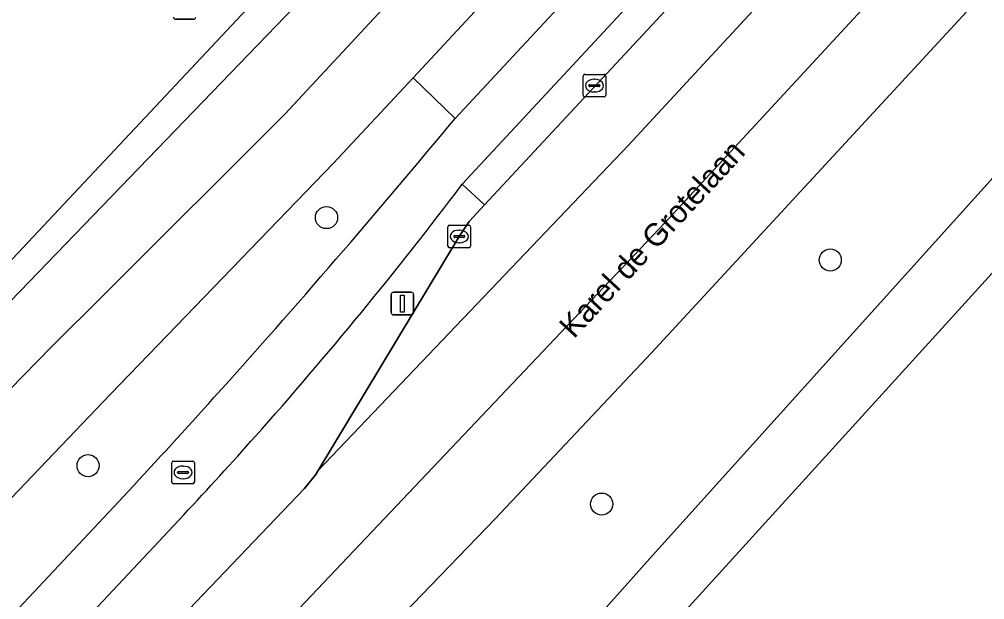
# Model space of a CAD drawing. Extents: x 159039 to 160102, y 381214 to 382524.
# Drawn here: x 159571.62 to 159614.28, y 381621.64 to 381647.3 of the extents above; entities that cross this region are included whole.
import ezdxf

# ---------------------------------------------------------------- set-up
doc = ezdxf.new("R2010")
doc.units = 0
for name, color, linetype in [('IMGEO_Afvalbak', 7, 'Continuous'), ('IMGEO_Berm_groen', 7, 'Continuous'), ('IMGEO_Boom', 7, 'Continuous'), ('IMGEO_Fietspad_gesloten', 7, 'Continuous'), ('IMGEO_Groenvoorziening', 7, 'Continuous'), ('IMGEO_Haag', 7, 'Continuous'), ('IMGEO_Kolk', 7, 'Continuous'), ('IMGEO_Lichtmast', 7, 'Continuous'), ('IMGEO_Openbare_ruimte_label', 7, 'Continuous'), ('IMGEO_OVBaan_gesloten', 7, 'Continuous'), ('IMGEO_Rijbaan_regionaal_gesloten', 7, 'Continuous'), ('IMGEO_Rioolput', 7, 'Continuous'), ('IMGEO_Voetpad_open', 7, 'Continuous')]:
    doc.layers.add(name, color=color, linetype=linetype)

msp = doc.modelspace()

# ---------------------------------------------------------------- linework, layer by layer
at = {"layer": 'IMGEO_Afvalbak'}
for p, q in [((159579.317, 381647.303), (159578.527, 381647.303)), ((159578.527, 381647.303), (159579.317, 381647.303))]:
    msp.add_line(p, q, dxfattribs=at)
for centre, start, end in [((159578.527, 381647.403), 180, 270), ((159578.527, 381647.403), 180, 270), ((159579.317, 381647.403), 270, 0), ((159579.317, 381647.403), 270, 0)]:
    msp.add_arc(centre, 0.1, start, end, dxfattribs=at)
at = {"layer": 'IMGEO_Berm_groen'}
for points in [[(159841.852, 381897.063), (159823.914, 381875.971), (159819.971, 381871.423), (159815.888, 381866.888), (159752.856, 381798.613), (159599.558, 381632.564), (159592.645, 381625.218), (159589.007, 381621.449), (159578.07, 381610.115), (159553.466, 381585.359)], [(159559.945, 381579.013), (159560.056, 381579.137), (159585.926, 381608.237), (159593.339, 381616.569), (159599.599, 381623.605), (159617.338, 381643.288), (159670.38, 381700.568), (159757.203, 381794.546)], [(159590.872, 381642.92), (159589.015, 381644.721), (159585.499, 381640.939), (159577.744, 381632.901), (159575.665, 381630.746), (159569.368, 381624.177), (159558.565, 381613.085), (159548.645, 381602.999), (159545.161, 381599.355), (159543.018, 381597.584), (159541.982, 381596.459), (159544.509, 381594.138), (159551.154, 381600.241), (159553.852, 381602.863), (159558.941, 381607.909), (159565.184, 381614.452), (159576.437, 381626.443)], [(159584.212, 381626.557), (159584.336, 381626.71), (159584.722, 381627.184), (159584.829, 381627.362), (159591.059, 381637.702), (159591.49, 381638.357), (159592.174, 381639.105), (159591.191, 381640.013)], [(159546.168, 381591.611), (159547.849, 381590.074), (159548.557, 381590.096), (159577.828, 381619.868), (159584.212, 381626.557)], [(159578.883, 381625.401), (159561.917, 381607.313)]]:
    msp.add_lwpolyline(points, dxfattribs=at)
for centre, radius, start, end in [((159286.321, 381895.111), 395.413, 318.01061, 320.37276), ((159447.443, 381748.616), 180.162, 318.3428, 322.92849), ((159274.657, 381905.991), 411.362, 317.19012, 317.97104), ((159449.828, 381746.393), 176.902, 316.84702, 318.36751)]:
    msp.add_arc(centre, radius, start, end, dxfattribs=at)
at = {"layer": 'IMGEO_Boom'}
for centre in [(159585.191, 381638.54), (159607.452, 381636.662), (159574.656, 381627.57), (159597.353, 381625.871)]:
    msp.add_circle(centre, 0.489, dxfattribs=at)
at = {"layer": 'IMGEO_Fietspad_gesloten'}
for points in [[(159835.156, 381908.672), (159832.541, 381905.347), (159832.075, 381904.754), (159821.782, 381892.503), (159813.565, 381883.06), (159802.783, 381871.052), (159791.475, 381858.62), (159743.819, 381807.067), (159624.348, 381677.828), (159617.523, 381670.775), (159605.021, 381658.14), (159590.872, 381642.92)], [(159591.191, 381640.013), (159607.377, 381657.444), (159619.167, 381669.166), (159626.019, 381676.247), (159694.686, 381750), (159745.746, 381805.265), (159767.026, 381828.298), (159776.532, 381838.557), (159790.971, 381854.296), (159805.539, 381870.374), (159816.536, 381882.828), (159825.133, 381893.111), (159830.877, 381899.559), (159834.614, 381904.005), (159837.348, 381907.14)], [(159576.437, 381626.443), (159565.184, 381614.452), (159558.941, 381607.909), (159553.852, 381602.863), (159551.154, 381600.241), (159544.509, 381594.138), (159544.059, 381593.709)], [(159561.917, 381607.313), (159578.883, 381625.401)]]:
    msp.add_lwpolyline(points, dxfattribs=at)
for centre, radius, start, end in [((159286.321, 381895.111), 395.413, 318.01061, 320.37276), ((159447.443, 381748.616), 180.162, 318.3428, 322.92849), ((159274.657, 381905.991), 411.362, 317.19012, 317.97104), ((159449.828, 381746.393), 176.902, 316.84702, 318.36751)]:
    msp.add_arc(centre, radius, start, end, dxfattribs=at)
at = {"layer": 'IMGEO_Groenvoorziening'}
for points in [[(159580.963, 381663.437), (159580.655, 381663.109), (159580.346, 381662.782), (159580.038, 381662.454), (159579.729, 381662.127), (159587.972, 381654.486), (159558.259, 381622.813), (159556.116, 381624.762), (159555.693, 381624.308), (159551.81, 381620.174), (159552.36, 381619.654), (159548.295, 381615.229), (159546.996, 381616.431), (159544.08, 381613.241), (159547.363, 381610.113), (159589.438, 381653.741), (159589.75, 381654.065), (159590.063, 381654.389), (159590.375, 381654.713), (159589.216, 381655.787)], [(159587.972, 381654.486), (159579.729, 381662.127), (159575.6, 381657.744), (159578.112, 381655.419), (159571.654, 381648.503), (159571.369, 381648.793), (159570.528, 381647.911), (159570.836, 381647.627), (159565.241, 381641.635), (159557.51, 381648.9), (159544.735, 381635.116), (159556.116, 381624.762), (159558.259, 381622.813)], [(159590.375, 381654.713), (159590.063, 381654.389), (159589.75, 381654.065), (159589.438, 381653.741), (159547.363, 381610.113), (159546.355, 381608.976), (159548.119, 381607.324), (159554.495, 381613.846), (159573.041, 381632.819), (159575.361, 381635.134), (159583.355, 381643.112), (159592.39, 381652.845)]]:
    msp.add_lwpolyline(points, close=True, dxfattribs=at)
at = {"layer": 'IMGEO_Haag'}
msp.add_lwpolyline([(159580.963, 381663.437), (159580.655, 381663.109), (159580.346, 381662.782), (159580.038, 381662.454), (159579.729, 381662.127), (159587.972, 381654.486), (159558.259, 381622.813), (159556.116, 381624.762), (159555.693, 381624.308), (159551.81, 381620.174), (159552.36, 381619.654), (159548.295, 381615.229), (159546.996, 381616.431), (159544.08, 381613.241), (159547.363, 381610.113), (159589.438, 381653.741), (159589.75, 381654.065), (159590.063, 381654.389), (159590.375, 381654.713), (159589.216, 381655.787)], close=True, dxfattribs=at)
at = {"layer": 'IMGEO_Kolk'}
for p, q in [((159596.531, 381643.944), (159596.531, 381644.796)), ((159596.606, 381644.87), (159597.458, 381644.87)), ((159597.019, 381644.65), (159597.044, 381644.65)), ((159597.532, 381644.796), (159597.532, 381643.944)), ((159596.79, 381644.364), (159596.79, 381644.376)), ((159597.228, 381644.327), (159596.83, 381644.327)), ((159596.833, 381644.413), (159597.231, 381644.413)), ((159597.042, 381644.09), (159597.017, 381644.09)), ((159597.274, 381644.376), (159597.274, 381644.364)), ((159597.458, 381643.87), (159596.606, 381643.87)), ((159590.558, 381637.276), (159590.558, 381638.128)), ((159590.633, 381638.202), (159591.485, 381638.202)), ((159591.559, 381638.128), (159591.559, 381637.276)), ((159590.817, 381637.696), (159590.817, 381637.708)), ((159590.86, 381637.745), (159591.258, 381637.745)), ((159591.046, 381637.982), (159591.071, 381637.982)), ((159591.301, 381637.708), (159591.301, 381637.696)), ((159591.255, 381637.659), (159590.857, 381637.659)), ((159591.069, 381637.422), (159591.044, 381637.422)), ((159591.485, 381637.202), (159590.633, 381637.202))]:
    msp.add_line(p, q, dxfattribs=at)
for points in [[(159596.531, 381643.944), (159596.531, 381644.796)], [(159596.606, 381644.87), (159597.458, 381644.87)], [(159597.532, 381644.796), (159597.532, 381643.944)], [(159597.458, 381643.87), (159596.606, 381643.87)], [(159590.558, 381637.276), (159590.558, 381638.128)], [(159590.633, 381638.202), (159591.485, 381638.202)], [(159591.559, 381638.128), (159591.559, 381637.276)], [(159591.485, 381637.202), (159590.633, 381637.202)]]:
    msp.add_lwpolyline(points, dxfattribs=at)
for centre, radius, start, end in [((159596.608, 381644.794), 0.0765, 91.552, 178.448), ((159596.608, 381644.794), 0.0765, 91.552, 178.448), ((159597.456, 381644.794), 0.0765, 1.552, 88.448), ((159597.456, 381644.794), 0.0765, 1.552, 88.448), ((159596.83, 381644.373), 0.0403, 85.8775, 175.7526), ((159596.827, 381644.363), 0.0366, 178.938, 274.7102), ((159597.231, 381644.37), 0.043, 264.8664, 352.4533), ((159597.235, 381644.375), 0.0386, 1.7309, 96.639), ((159596.608, 381643.946), 0.0765, 181.552, 268.448), ((159596.608, 381643.946), 0.0765, 181.552, 268.448), ((159597.456, 381643.946), 0.0765, 271.552, 358.448), ((159597.456, 381643.946), 0.0765, 271.552, 358.448), ((159590.635, 381638.126), 0.0765, 91.552, 178.448), ((159590.635, 381638.126), 0.0765, 91.552, 178.448), ((159591.483, 381638.126), 0.0765, 1.552, 88.448), ((159591.483, 381638.126), 0.0765, 1.552, 88.448), ((159590.857, 381637.705), 0.0403, 85.8775, 175.7526), ((159590.854, 381637.695), 0.0366, 178.938, 274.7102), ((159591.258, 381637.702), 0.043, 264.8664, 352.4533), ((159591.262, 381637.707), 0.0386, 1.7309, 96.639), ((159590.635, 381637.278), 0.0765, 181.552, 268.448), ((159590.635, 381637.278), 0.0765, 181.552, 268.448), ((159591.483, 381637.278), 0.0765, 271.552, 358.448), ((159591.483, 381637.278), 0.0765, 271.552, 358.448)]:
    msp.add_arc(centre, radius, start, end, dxfattribs=at)
for centre, major_axis, ratio, start_param, end_param in [((159597.018, 381644.37), (-0.387, 0.002), 0.722429, 4.712389, 7.853982), ((159597.043, 381644.37), (-0.39, 0.002), 0.717154, 1.570796, 4.712389), ((159591.045, 381637.702), (-0.387, 0.002), 0.722429, 4.712389, 7.853982), ((159591.07, 381637.702), (-0.39, 0.002), 0.717154, 1.570796, 4.712389)]:
    msp.add_ellipse(centre, major_axis=major_axis, ratio=ratio, start_param=start_param, end_param=end_param, dxfattribs=at)
at = {"layer": 'IMGEO_Lichtmast'}
for p, q in [((159588.048, 381634.337), (159588.048, 381635.137)), ((159588.048, 381635.137), (159588.048, 381634.337)), ((159588.148, 381635.237), (159588.938, 381635.237)), ((159588.938, 381635.237), (159588.148, 381635.237)), ((159589.038, 381635.137), (159589.038, 381634.337)), ((159589.038, 381634.337), (159589.038, 381635.137)), ((159588.938, 381634.237), (159588.148, 381634.237)), ((159588.148, 381634.237), (159588.938, 381634.237))]:
    msp.add_line(p, q, dxfattribs=at)
msp.add_lwpolyline([(159588.468, 381635.112), (159588.618, 381635.112), (159588.618, 381634.362), (159588.468, 381634.362), (159588.468, 381635.112)], dxfattribs=at)
for centre, start, end in [((159588.148, 381635.137), 90, 180), ((159588.148, 381635.137), 90, 180), ((159588.938, 381635.137), 0, 90), ((159588.938, 381635.137), 360, 90), ((159588.148, 381634.337), 180, 270), ((159588.148, 381634.337), 180, 270), ((159588.938, 381634.337), 270, 0), ((159588.938, 381634.337), 270, 0)]:
    msp.add_arc(centre, 0.1, start, end, dxfattribs=at)
at = {"layer": 'IMGEO_OVBaan_gesloten'}
msp.add_lwpolyline([(159609.675, 381657.749), (159608.957, 381657.159), (159608.375, 381656.525), (159592.174, 381639.105), (159591.49, 381638.357), (159591.059, 381637.702), (159584.829, 381627.362), (159598.538, 381641.746), (159612.101, 381656.417), (159626.106, 381671.356)], dxfattribs=at)
at = {"layer": 'IMGEO_Rijbaan_regionaal_gesloten'}
msp.add_lwpolyline([(159578.07, 381610.115), (159589.007, 381621.449), (159592.645, 381625.218), (159599.558, 381632.564), (159752.856, 381798.613), (159815.888, 381866.888), (159819.971, 381871.423), (159823.914, 381875.971), (159841.852, 381897.063), (159839.399, 381899.421), (159826.472, 381884.273), (159785.146, 381838.389), (159750.398, 381800.912), (159745.744, 381795.892), (159710.343, 381757.399), (159678.405, 381722.986), (159648.315, 381690.343), (159630.229, 381670.866), (159600.138, 381638.3), (159586.667, 381624.085), (159574.896, 381611.663), (159550.989, 381587.747), (159553.466, 381585.359)], close=True, dxfattribs=at)
for points in [[(159791.175, 381831.318), (159757.203, 381794.546), (159670.38, 381700.568), (159617.338, 381643.288), (159599.599, 381623.605), (159593.339, 381616.569), (159585.926, 381608.237), (159560.056, 381579.137), (159559.945, 381579.013), (159561.472, 381577.6), (159571.505, 381588.644), (159709.596, 381740.644), (159814.994, 381851.76), (159819, 381856.018), (159822.889, 381860.084)], [(159743.207, 381798.451), (159627.477, 381673.139), (159626.106, 381671.356), (159612.101, 381656.417), (159598.538, 381641.746), (159584.829, 381627.362), (159584.722, 381627.184), (159584.336, 381626.71), (159584.212, 381626.557), (159577.828, 381619.868), (159548.557, 381590.096), (159550.989, 381587.747), (159574.896, 381611.663), (159586.667, 381624.085), (159600.138, 381638.3), (159630.229, 381670.866), (159648.315, 381690.343), (159678.405, 381722.986)]]:
    msp.add_lwpolyline(points, dxfattribs=at)
at = {"layer": 'IMGEO_Rioolput'}
for p, q in [((159578.352, 381626.844), (159578.352, 381627.696)), ((159578.427, 381627.77), (159579.279, 381627.77)), ((159578.84, 381627.55), (159578.865, 381627.55)), ((159579.353, 381627.696), (159579.353, 381626.844)), ((159578.611, 381627.264), (159578.611, 381627.276)), ((159579.049, 381627.227), (159578.651, 381627.227)), ((159578.654, 381627.313), (159579.052, 381627.313)), ((159579.095, 381627.276), (159579.095, 381627.264)), ((159579.279, 381626.77), (159578.427, 381626.77)), ((159578.863, 381626.99), (159578.838, 381626.99))]:
    msp.add_line(p, q, dxfattribs=at)
for points in [[(159578.352, 381626.844), (159578.352, 381627.696)], [(159578.427, 381627.77), (159579.279, 381627.77)], [(159579.353, 381627.696), (159579.353, 381626.844)], [(159579.279, 381626.77), (159578.427, 381626.77)]]:
    msp.add_lwpolyline(points, dxfattribs=at)
for centre, radius, start, end in [((159578.429, 381627.694), 0.0765, 91.552, 178.448), ((159578.429, 381627.694), 0.0765, 91.552, 178.448), ((159579.277, 381627.694), 0.0765, 1.552, 88.448), ((159579.277, 381627.694), 0.0765, 1.552, 88.448), ((159578.651, 381627.273), 0.0403, 85.8775, 175.7526), ((159578.648, 381627.263), 0.0366, 178.938, 274.7102), ((159579.052, 381627.27), 0.043, 264.8664, 352.4533), ((159579.056, 381627.275), 0.0386, 1.7309, 96.639), ((159578.429, 381626.846), 0.0765, 181.552, 268.448), ((159578.429, 381626.846), 0.0765, 181.552, 268.448), ((159579.277, 381626.846), 0.0765, 271.552, 358.448), ((159579.277, 381626.846), 0.0765, 271.552, 358.448)]:
    msp.add_arc(centre, radius, start, end, dxfattribs=at)
for centre, major_axis, ratio, start_param, end_param in [((159578.839, 381627.27), (-0.387, 0.002), 0.722429, 4.712389, 7.853982), ((159578.864, 381627.27), (-0.39, 0.002), 0.717154, 1.570796, 4.712389)]:
    msp.add_ellipse(centre, major_axis=major_axis, ratio=ratio, start_param=start_param, end_param=end_param, dxfattribs=at)
at = {"layer": 'IMGEO_Voetpad_open'}
for points in [[(159569.368, 381624.177), (159575.665, 381630.746), (159577.744, 381632.901), (159585.499, 381640.939), (159589.015, 381644.721), (159603.212, 381659.994), (159607.381, 381664.479), (159686.466, 381750)], [(159648.524, 381713.555), (159603.909, 381665.258), (159601.849, 381663.049), (159593.32, 381653.858), (159592.39, 381652.845), (159583.355, 381643.112), (159575.361, 381635.134), (159573.041, 381632.819), (159554.495, 381613.846)]]:
    msp.add_lwpolyline(points, dxfattribs=at)
for points in [[(159605.021, 381658.14), (159603.743, 381659.401), (159603.212, 381659.994), (159589.015, 381644.721), (159590.872, 381642.92)], [(159608.375, 381656.525), (159607.377, 381657.444), (159591.191, 381640.013), (159592.174, 381639.105)]]:
    msp.add_lwpolyline(points, close=True, dxfattribs=at)

# ---------------------------------------------------------------- texts
at = {"layer": 'IMGEO_Openbare_ruimte_label'}
msp.add_text('Karel de Grotelaan', height=1, rotation=47.187, dxfattribs=at).set_placement((159596.125, 381633.148))

doc.saveas('drawing.dxf')
